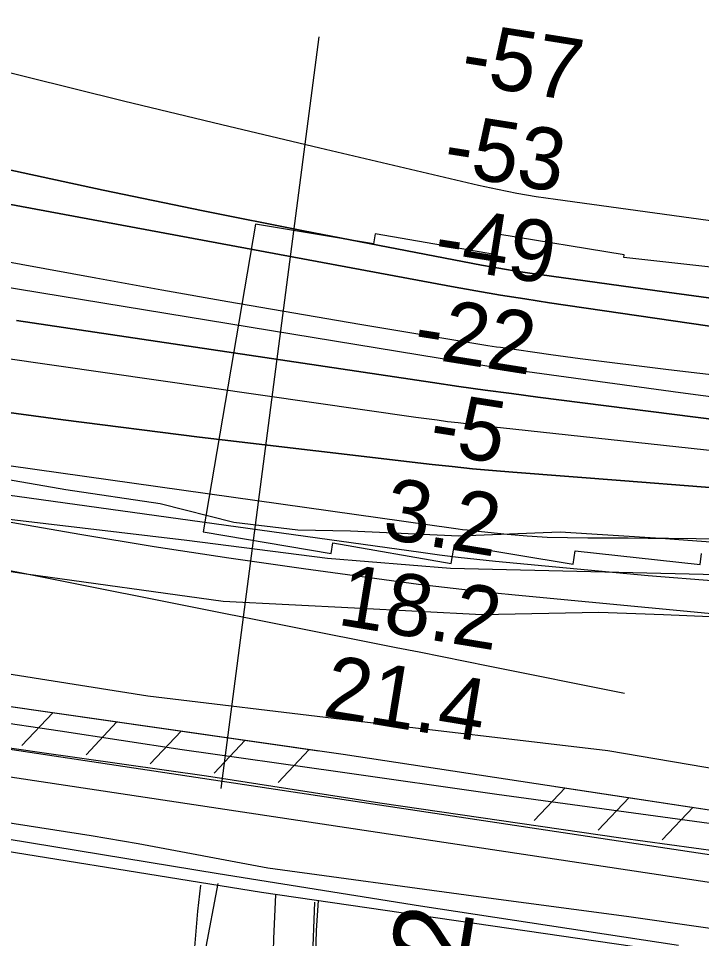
# Model space of a CAD drawing. Extents: x 3508733 to 3546731, y 546897 to 572481.
# Drawn here: x 3529654 to 3530393, y 562032 to 563028 of the extents above; entities that cross this region are included whole.
import ezdxf

# ---------------------------------------------------------------- set-up
doc = ezdxf.new("R2010")
doc.units = 0
for name, color, linetype in [('V-FLOD-BASE', 7, 'Continuous'), ('V-LEVE-TOET', 7, 'Continuous'), ('V-RIVR-EDGE', 7, 'Continuous'), ('V-RIVR-RANG', 7, 'Continuous'), ('V-RIVR-RANG-IDEN', 7, 'Continuous'), ('V-ROAD-CNTR', 7, 'Continuous'), ('V-RRAP-FSHR', 7, 'Continuous'), ('V-RRAP-RVMT', 7, 'Continuous'), ('V-SITE-VEGE', 7, 'Continuous'), ('V-SURV-LINE', 7, 'Continuous'), ('V-TOPO-DPTH', 7, 'Continuous'), ('V-TOPO-MAJR', 7, 'Continuous'), ('V-TOPO-MINR', 7, 'Continuous'), ('V-TOPO-SHOR', 7, 'Continuous'), ('V-TOPO-WATR', 7, 'Continuous')]:
    doc.layers.add(name, color=color, linetype=linetype)

msp = doc.modelspace()

# ---------------------------------------------------------------- linework, layer by layer
at = {"layer": 'V-FLOD-BASE'}
msp.add_lwpolyline([(3530489.92, 562116.04), (3530305.84, 562141.22), (3530045.14, 562178.82), (3529857.68, 562208.13), (3529677.04, 562233.95), (3529458.08, 562265.65), (3529266.5, 562294.32), (3529003.07, 562332.64), (3528961.99, 562336.48), (3528834.7, 562352.85), (3528773.79, 562360.32)], dxfattribs=at)
at = {"layer": 'V-LEVE-TOET'}
for points in [[(3528672.81, 562414.76), (3528695.02, 562412.91), (3528713.51, 562411.35), (3528775.77, 562401.12), (3528922.89, 562381.12), (3528961.21, 562375.94), (3528977.61, 562371.66), (3529013.13, 562359.65), (3529041.18, 562355.94), (3529183.5, 562334.62), (3529331.3, 562313.93), (3529542.7, 562280.25), (3529699.4, 562257.42), (3529831.44, 562236.88), (3529999.77, 562213.24), (3530171.52, 562188.88), (3530483.18, 562146.08)], [(3530477.56, 562032.63), (3530311.97, 562056.24), (3530146.36, 562078.49), (3529923.96, 562108.84), (3529783.75, 562134.94), (3529733.13, 562143.68), (3529638.03, 562158.35)]]:
    msp.add_lwpolyline(points, dxfattribs=at)
at = {"layer": 'V-RIVR-EDGE'}
msp.add_lwpolyline([(3529541.69, 562546.97), (3529705.51, 562518.35), (3529807.53, 562503.09), (3529887.32, 562483.08), (3529956.34, 562474.51), (3530013.37, 562473.77), (3530130.41, 562468.07), (3530240.29, 562472.61), (3530348.93, 562465.73), (3530490.58, 562455.18), (3530568.01, 562448.98), (3530601.03, 562453.1), (3530674.86, 562445.72), (3530817.71, 562438.16), (3530969.58, 562431.18), (3531114.84, 562422.42), (3531239.12, 562428.11), (3531343.6, 562438.66), (3531383.86, 562452.97), (3531434.33, 562469.05), (3531515.35, 562459.85)], dxfattribs=at)
at = {"layer": 'V-RIVR-RANG'}
msp.add_line((3529873.58, 562195.03), (3529979.5, 563008.16), dxfattribs=at)
at = {"layer": 'V-ROAD-CNTR'}
for points in [[(3530757.8, 561962.61), (3530375.42, 562015.55), (3529917.18, 562082.35), (3529550.36, 562141.59), (3529261.23, 562190.2), (3528940.49, 562241.68), (3528483.42, 562309.97), (3528326.5, 562333.88), (3528176.04, 562360.42)], [(3529869.83, 562092.25), (3529842.02, 561943.45), (3529823.26, 561807.79), (3529826.19, 561683.97), (3529822.88, 561550.49)], [(3529851.22, 562090.27), (3529847.91, 562062.17), (3529840.65, 561975.48), (3529829.66, 561848.78), (3529828.25, 561833.71), (3529827.07, 561818.63), (3529826.12, 561803.52), (3529825.4, 561788.41), (3529824.92, 561773.28), (3529824.67, 561758.15), (3529824.65, 561743.02), (3529824.86, 561727.88), (3529825.11, 561626.84), (3529825, 561515.08)], [(3529928.52, 561950.3), (3529930.63, 562032.69), (3529932.6, 562079.97)], [(3529942.72, 561533.66), (3529943.94, 561641.12), (3529961.44, 561724.36), (3529964.67, 561806.67), (3529974.74, 562072.04)], [(3529978.45, 562073.79), (3529976.4, 562041.41), (3529973.65, 561947.29)]]:
    msp.add_lwpolyline(points, dxfattribs=at)
at = {"layer": 'V-RRAP-FSHR'}
for p, q in [((3529691.56, 562276.87), (3529658.16, 562241.25)), ((3529760.85, 562266.94), (3529727.45, 562231.32)), ((3529830.14, 562257.01), (3529796.74, 562221.39)), ((3529899.43, 562247.09), (3529866.03, 562211.46)), ((3529968.72, 562237.16), (3529935.33, 562201.53)), ((3530245.61, 562195.5), (3530211.92, 562160.15)), ((3530314.82, 562185.01), (3530281.13, 562149.66)), ((3530384.03, 562174.53), (3530350.34, 562139.17))]:
    msp.add_line(p, q, dxfattribs=at)
for points in [[(3523475.51, 563626.12), (3524086.43, 563502.35), (3525193.25, 563274.55), (3526957.47, 562942.62), (3528202.6, 562690.37), (3529085.86, 562552.33), (3529836.46, 562463.4), (3529988.49, 562444.1), (3530121.42, 562433.28), (3530591.94, 562422.1), (3531229.94, 562384.23)], [(3528991.17, 562377.49), (3529520.03, 562301.45), (3529979.32, 562235.64)], [(3529520.03, 562301.45), (3530005.39, 562231.9), (3530463.26, 562162.52), (3530652.17, 562124.72), (3530699.67, 562125.28), (3530728.12, 562143.47), (3530785.02, 562179.86), (3530835.73, 562162.04), (3530871.39, 562134.3), (3530902.91, 562112.43), (3531136.15, 562100.24), (3531507.83, 562104.77), (3531883.57, 562094.27), (3532389.29, 562081.34), (3532875.91, 562077.71), (3533344.93, 562059.99), (3533650.72, 562055.72), (3533887.4, 562059.37), (3534147.49, 562076.22), (3534367.53, 562084.97), (3534626.01, 562110.18), (3534901.97, 562131.95), (3535007.86, 562142.19), (3535007.92, 562141.08)], [(3530235.1, 562197.09), (3530463.26, 562162.52), (3530652.17, 562124.72), (3530699.67, 562125.28), (3530728.12, 562143.47), (3530785.02, 562179.86), (3530835.73, 562162.04), (3530871.39, 562134.3), (3530902.91, 562112.43), (3530933.7, 562110.82)]]:
    msp.add_lwpolyline(points, dxfattribs=at)
at = {"layer": 'V-RRAP-RVMT'}
for p, q in [((3529910.54, 562805.48), (3529853.93, 562472.42)), ((3530038.31, 562783.93), (3529910.54, 562805.48)), ((3530040.17, 562795.03), (3530038.31, 562783.93)), ((3530169.13, 562772.6), (3530040.17, 562795.03)), ((3530172.66, 562794.59), (3530169.13, 562772.6)), ((3530309.42, 562772.03), (3530172.66, 562794.59)), ((3530308.93, 562769.16), (3530309.42, 562772.03)), ((3530417.23, 562757.21), (3530308.93, 562769.16)), ((3529853.93, 562472.42), (3529992.35, 562448.93)), ((3529992.35, 562448.93), (3529994.38, 562460.74)), ((3529994.38, 562460.74), (3530122.44, 562438.44)), ((3530122.44, 562438.44), (3530125.89, 562458.77)), ((3530125.89, 562458.77), (3530254.1, 562437.52)), ((3530254.1, 562437.52), (3530256.47, 562451.9)), ((3530256.47, 562451.9), (3530391.69, 562437.02)), ((3530391.69, 562437.02), (3530393.09, 562449.15))]:
    msp.add_line(p, q, dxfattribs=at)
at = {"layer": 'V-SITE-VEGE'}
for points in [[(3529502.45, 562451.59), (3529662.74, 562427.03), (3529875.73, 562397.34), (3530017.85, 562390.16), (3530155.54, 562383.25), (3530282.09, 562385.79), (3530352.01, 562383.16), (3530486.34, 562377.16)], [(3530484.57, 562202.7), (3530291.87, 562235.62), (3530004.39, 562269.51), (3529794.41, 562294.58), (3529479.96, 562344.41)]]:
    msp.add_lwpolyline(points, dxfattribs=at)
at = {"layer": 'V-SURV-LINE'}
for points in [[(3528223.45, 562451.64), (3530786.45, 562065.48)], [(3530781.99, 562035.81), (3528219, 562421.98)]]:
    msp.add_lwpolyline(points, dxfattribs=at)
at = {"layer": 'V-TOPO-DPTH'}
for points in [[(3532287.17, 562499.34), (3531412.28, 562566.65), (3531363.61, 562570.58), (3531314.97, 562574.76), (3531266.36, 562579.3), (3531217.77, 562584.09), (3531188.66, 562587.07), (3531154.65, 562590.63), (3531120.66, 562594.29), (3531086.68, 562598.11), (3531052.72, 562602.03), (3531018.78, 562606.17), (3530984.87, 562610.5), (3530950.99, 562615.11), (3530917.14, 562619.91), (3530228.55, 562720.38), (3530202, 562724.42), (3530175.49, 562728.65), (3530149.03, 562733.2), (3530122.61, 562737.95), (3529232.88, 562903.29)], [(3529232.88, 562903.29), (3530122.61, 562737.95), (3530149.03, 562733.2), (3530175.49, 562728.65), (3530202, 562724.42), (3530228.55, 562720.38), (3530917.14, 562619.91), (3530950.99, 562615.11), (3530984.87, 562610.5), (3531018.78, 562606.17), (3531052.72, 562602.03), (3531086.68, 562598.11), (3531120.66, 562594.29), (3531154.65, 562590.63), (3531188.66, 562587.07), (3531217.77, 562584.09), (3531266.36, 562579.3), (3531314.97, 562574.76), (3531363.61, 562570.58), (3531412.28, 562566.65), (3532287.17, 562499.34)], [(3528959.88, 562889.67), (3529737.89, 562747.15), (3529809.24, 562734.26), (3529880.62, 562721.6), (3529952.07, 562709.29), (3530023.56, 562697.2), (3530157.55, 562674.89), (3530162.08, 562674.15), (3530166.6, 562673.44), (3530171.14, 562672.76), (3530175.67, 562672.11), (3530230.11, 562664.5), (3530261.89, 562660.16), (3530293.68, 562655.97), (3530325.5, 562651.99), (3530357.34, 562648.16), (3531093.71, 562561.99), (3531104.74, 562560.73), (3531115.77, 562559.52), (3531126.81, 562558.38), (3531137.86, 562557.29), (3531899.62, 562484.28)], [(3528959.88, 562889.67), (3529737.89, 562747.15), (3529809.24, 562734.26), (3529880.62, 562721.6), (3529952.07, 562709.29), (3530023.56, 562697.2), (3530157.55, 562674.89), (3530162.08, 562674.15), (3530166.6, 562673.44), (3530171.14, 562672.76), (3530175.67, 562672.11), (3530230.11, 562664.5), (3530261.89, 562660.16), (3530293.68, 562655.97), (3530325.5, 562651.99), (3530357.34, 562648.16), (3531093.71, 562561.99), (3531104.74, 562560.73), (3531115.77, 562559.52), (3531126.81, 562558.38), (3531137.86, 562557.29), (3531899.62, 562484.28)], [(3531750.52, 562572.53), (3531188.76, 562635.6), (3531158.1, 562639.03), (3531127.44, 562642.42), (3531096.77, 562645.79), (3531066.1, 562649.12), (3530707.2, 562687.94), (3530619.15, 562697.89), (3530531.16, 562708.39), (3530443.27, 562719.73), (3530355.46, 562731.62), (3530204.93, 562752.73), (3530192.44, 562754.58), (3530179.98, 562756.55), (3530167.55, 562758.72), (3530155.14, 562761.01), (3529962.71, 562798.09), (3529854.23, 562819.64), (3529745.93, 562842.01), (3529637.89, 562865.61)], [(3531750.52, 562572.53), (3531188.76, 562635.6), (3531158.1, 562639.03), (3531127.44, 562642.42), (3531096.77, 562645.79), (3531066.1, 562649.12), (3530707.2, 562687.94), (3530619.15, 562697.89), (3530531.16, 562708.39), (3530443.27, 562719.73), (3530355.46, 562731.62), (3530204.93, 562752.73), (3530192.44, 562754.58), (3530179.98, 562756.55), (3530167.55, 562758.72), (3530155.14, 562761.01), (3529962.71, 562798.09), (3529854.23, 562819.64), (3529745.93, 562842.01), (3529637.89, 562865.61)], [(3531531.61, 562473.89), (3531390.67, 562485.74), (3531180.36, 562504.08), (3531144.62, 562507.3), (3531108.89, 562510.66), (3531073.17, 562514.23), (3531037.48, 562517.93), (3530974.02, 562524.71), (3530906.62, 562532.11), (3530839.26, 562539.78), (3530771.94, 562547.86), (3530704.66, 562556.21), (3530216.03, 562618.32), (3530187.48, 562622.04), (3530158.95, 562625.89), (3530130.44, 562629.91), (3530101.96, 562634.06), (3529804.67, 562678.34), (3529652.39, 562701.25)], [(3529652.39, 562701.25), (3529804.67, 562678.34), (3530101.96, 562634.06), (3530130.44, 562629.91), (3530158.95, 562625.89), (3530187.48, 562622.04), (3530216.03, 562618.32), (3530704.66, 562556.21), (3530771.94, 562547.86), (3530839.26, 562539.78), (3530906.62, 562532.11), (3530974.02, 562524.71), (3531037.48, 562517.93), (3531073.17, 562514.23), (3531108.89, 562510.66), (3531144.62, 562507.3), (3531180.36, 562504.08), (3531390.67, 562485.74), (3531531.61, 562473.89)], [(3531548.11, 562434.83), (3531458.96, 562440.44), (3531369.83, 562446.38), (3531280.71, 562452.53), (3531119.83, 562463.92), (3531111.17, 562464.55), (3531102.5, 562465.19), (3531093.84, 562465.85), (3531085.18, 562466.52), (3530639.81, 562501.77), (3530557.39, 562508.27), (3530474.95, 562514.75), (3530392.52, 562521.19), (3530310.08, 562527.61), (3530188.92, 562537.02), (3530167.08, 562538.84), (3530145.25, 562540.84), (3530123.45, 562543.09), (3530101.66, 562545.52), (3529850.03, 562575.07), (3529702.6, 562593.51), (3529555.38, 562613.41)], [(3531548.11, 562434.83), (3531458.96, 562440.44), (3531369.83, 562446.38), (3531280.71, 562452.53), (3531119.83, 562463.92), (3531111.17, 562464.55), (3531102.5, 562465.19), (3531093.84, 562465.85), (3531085.18, 562466.52), (3530639.81, 562501.77), (3530557.39, 562508.27), (3530474.95, 562514.75), (3530392.52, 562521.19), (3530310.08, 562527.61), (3530188.92, 562537.02), (3530167.08, 562538.84), (3530145.25, 562540.84), (3530123.45, 562543.09), (3530101.66, 562545.52), (3529850.03, 562575.07), (3529702.6, 562593.51), (3529555.38, 562613.41)], [(3529566.83, 562522.98), (3530089.47, 562450.36), (3530109.66, 562447.69), (3530129.87, 562445.19), (3530150.11, 562442.96), (3530170.37, 562440.9), (3530335.2, 562425.23), (3530408.48, 562419.52)]]:
    msp.add_lwpolyline(points, dxfattribs=at)
at = {"layer": 'V-TOPO-MAJR'}
msp.add_lwpolyline([(3529556.04, 562991.85), (3529661.94, 562965.11), (3529767.95, 562938.81), (3529874.12, 562913.13), (3529980.39, 562887.88), (3530151.78, 562847.69), (3530172.48, 562843.14), (3530193.26, 562838.98), (3530214.15, 562835.42), (3530235.12, 562832.24), (3530567.72, 562786.66)], dxfattribs=at)
at = {"layer": 'V-TOPO-MINR'}
for points in [[(3529232.88, 562903.29), (3530122.61, 562737.95), (3530149.03, 562733.2), (3530175.49, 562728.65), (3530202, 562724.42), (3530228.55, 562720.38), (3530917.14, 562619.91), (3530950.99, 562615.11), (3530984.87, 562610.5), (3531018.78, 562606.17), (3531052.72, 562602.03), (3531086.68, 562598.11), (3531120.66, 562594.29), (3531154.65, 562590.63), (3531188.66, 562587.07), (3531217.77, 562584.09), (3531266.36, 562579.3), (3531314.97, 562574.76), (3531363.61, 562570.58), (3531412.28, 562566.65), (3532287.17, 562499.34)], [(3528959.88, 562889.67), (3529737.89, 562747.15), (3529809.24, 562734.26), (3529880.62, 562721.6), (3529952.07, 562709.29), (3530023.56, 562697.2), (3530157.55, 562674.89), (3530162.08, 562674.15), (3530166.6, 562673.44), (3530171.14, 562672.76), (3530175.67, 562672.11), (3530230.11, 562664.5), (3530261.89, 562660.16), (3530293.68, 562655.97), (3530325.5, 562651.99), (3530357.34, 562648.16), (3531093.71, 562561.99), (3531104.74, 562560.73), (3531115.77, 562559.52), (3531126.81, 562558.38), (3531137.86, 562557.29), (3531899.62, 562484.28)], [(3529637.89, 562865.61), (3529745.93, 562842.01), (3529854.23, 562819.64), (3529962.71, 562798.09), (3530155.14, 562761.01), (3530167.55, 562758.72), (3530179.98, 562756.55), (3530192.44, 562754.58), (3530204.93, 562752.73), (3530355.46, 562731.62), (3530443.27, 562719.73), (3530531.16, 562708.39), (3530619.15, 562697.89), (3530707.2, 562687.94), (3531066.1, 562649.12), (3531096.77, 562645.79), (3531127.44, 562642.42), (3531158.1, 562639.03), (3531188.76, 562635.6), (3531750.52, 562572.53)], [(3529222.14, 562806.18), (3530132.3, 562656.68), (3530147.71, 562654.21), (3530163.13, 562651.83), (3530178.56, 562649.57), (3530194.01, 562647.4), (3530370.12, 562623.34), (3530473.68, 562609.61), (3530577.31, 562596.41), (3530681.04, 562584.01), (3530784.83, 562572.15), (3531066.91, 562541.03), (3531089.69, 562538.58), (3531112.49, 562536.22), (3531135.3, 562534), (3531158.11, 562531.86), (3532022.93, 562453.4)], [(3528965.57, 562757.23), (3530084.12, 562596.68), (3530095.56, 562595.08), (3530107, 562593.53), (3530118.45, 562592.05), (3530129.91, 562590.62), (3530141.38, 562589.25), (3530152.84, 562587.91), (3530164.32, 562586.61), (3530175.79, 562585.35), (3531073.49, 562487.96)], [(3529652.39, 562701.25), (3529804.67, 562678.34), (3530101.96, 562634.06), (3530130.44, 562629.91), (3530158.95, 562625.89), (3530187.48, 562622.04), (3530216.03, 562618.32), (3530704.66, 562556.21), (3530771.94, 562547.86), (3530839.26, 562539.78), (3530906.62, 562532.11), (3530974.02, 562524.71), (3531037.48, 562517.93), (3531073.17, 562514.23), (3531108.89, 562510.66), (3531144.62, 562507.3), (3531180.36, 562504.08), (3531390.67, 562485.74), (3531531.61, 562473.89)], [(3528899.27, 562649.17), (3530124.7, 562476.42), (3530129.7, 562475.74), (3530134.7, 562475.11), (3530139.71, 562474.53), (3530144.73, 562474), (3530182.73, 562470.17), (3530204.48, 562468.32), (3530226.26, 562466.92), (3530248.08, 562466.21), (3530269.91, 562465.94), (3530291.76, 562465.97), (3530313.61, 562465.94), (3530335.46, 562465.81), (3530357.31, 562465.62), (3530536.54, 562463.66)], [(3528589.52, 562625.87), (3528609.89, 562624.64), (3528660.39, 562618.91), (3528710.74, 562611.4), (3528814.55, 562593.1), (3528829.07, 562590.5), (3528843.58, 562587.86), (3528858.08, 562585.13), (3528872.57, 562582.36), (3529093.28, 562539.49), (3529218.09, 562515.15), (3529342.89, 562490.7), (3529467.65, 562466.06), (3529592.38, 562441.29), (3530062.79, 562347.55), (3530087.69, 562342.59), (3530112.58, 562337.61), (3530137.46, 562332.61), (3530162.35, 562327.61), (3530309.83, 562297.91)], [(3529566.83, 562522.98), (3530089.47, 562450.36), (3530109.66, 562447.69), (3530129.87, 562445.19), (3530150.11, 562442.96), (3530170.37, 562440.9), (3530335.2, 562425.23), (3530408.48, 562419.52)], [(3529640.16, 562484.13), (3529720.56, 562470.01), (3529801.07, 562456.62), (3529881.76, 562444.32), (3529962.56, 562432.75), (3530049.81, 562420.86), (3530087.1, 562416.01), (3530124.43, 562411.47), (3530161.81, 562407.39), (3530199.22, 562403.61), (3530616.31, 562364.09)]]:
    msp.add_lwpolyline(points, dxfattribs=at)
at = {"layer": 'V-TOPO-SHOR'}
msp.add_lwpolyline([(3528983.22, 562242.45), (3529157.22, 562216.76), (3529382.35, 562179.62), (3529591.14, 562148.79), (3529870.16, 562102.9), (3530089.16, 562067.88), (3530368.22, 562025.4)], dxfattribs=at)
at = {"layer": 'V-TOPO-WATR'}
msp.add_lwpolyline([(3529555.38, 562613.41), (3529702.6, 562593.51), (3529850.03, 562575.07), (3530101.66, 562545.52), (3530123.45, 562543.09), (3530145.25, 562540.84), (3530167.08, 562538.84), (3530188.92, 562537.02), (3530310.08, 562527.61), (3530392.52, 562521.19), (3530474.95, 562514.75), (3530557.39, 562508.27), (3530639.81, 562501.77), (3531085.18, 562466.52), (3531093.84, 562465.85), (3531102.5, 562465.19), (3531111.17, 562464.55), (3531119.83, 562463.92), (3531280.71, 562452.53), (3531369.83, 562446.38), (3531458.96, 562440.44), (3531548.11, 562434.83)], dxfattribs=at)

# ---------------------------------------------------------------- texts
at = {"layer": 'V-RIVR-RANG'}
for s, rotation, p in [('-57', 351.00231, (3530130.73, 562958.16)), ('-53', 351.00231, (3530111.99, 562859.88)), ('-49', 351.00231, (3530101.58, 562760.28)), ('-22', 351.00231, (3530079.7, 562662.5)), ('-5', 351.00231, (3530096.65, 562558.57)), ('3.2', 350.71833, (3530046.54, 562465.69)), ('18.2', 350.71833, (3529997.85, 562372.32)), ('21.4', 350.71833, (3529981.97, 562273.59))]:
    msp.add_text(s, height=67, rotation=rotation, dxfattribs=at).set_placement(p)
at = {"layer": 'V-RIVR-RANG-IDEN'}
msp.add_text('R-137.2', height=83, rotation=80.86063, dxfattribs=at).set_placement((3530084.91, 561669.89))

doc.saveas('drawing.dxf')
